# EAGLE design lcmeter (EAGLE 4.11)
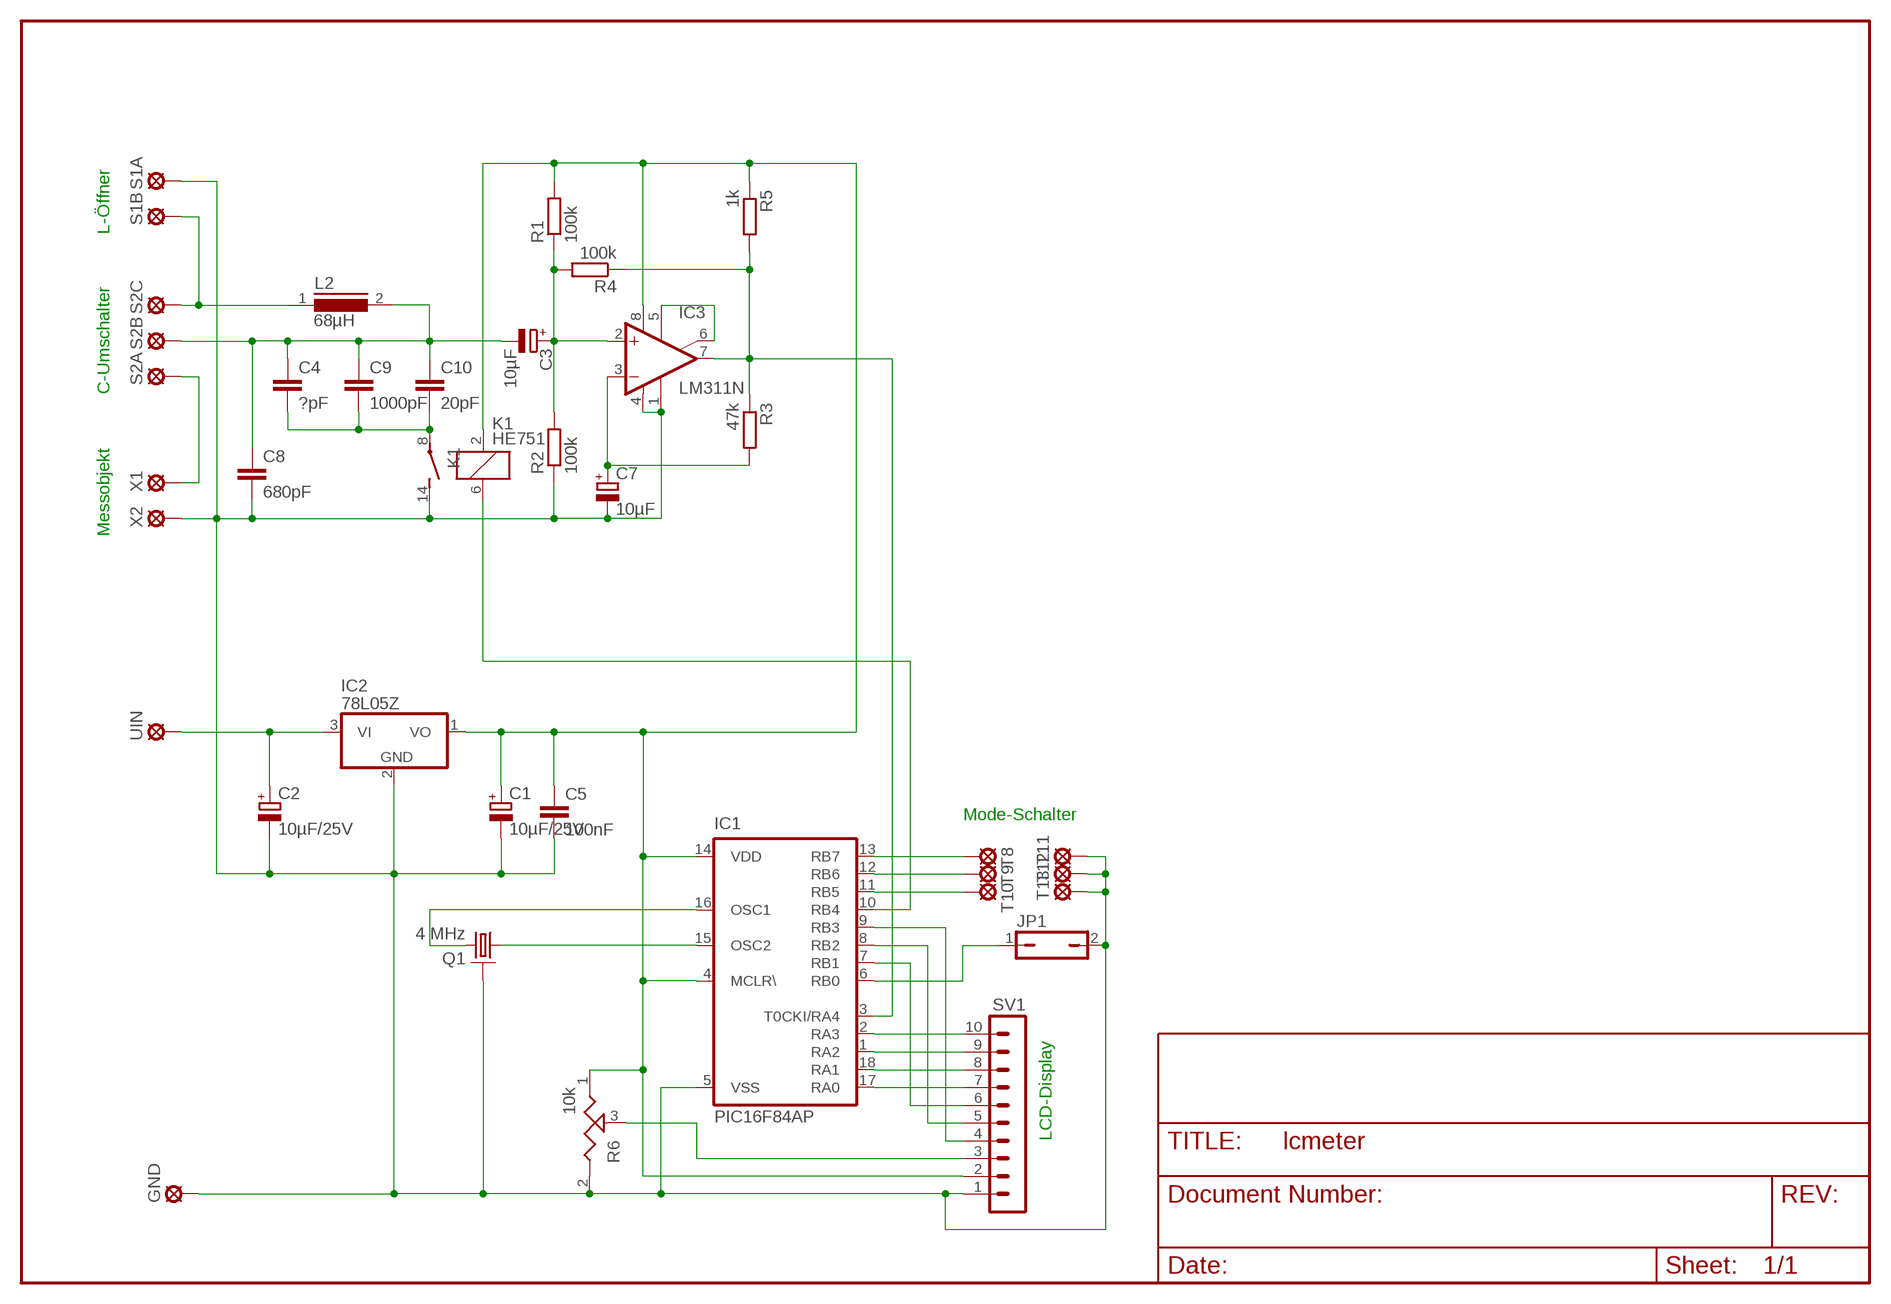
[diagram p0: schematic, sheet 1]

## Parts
C1  10µF/25V  CPOL-EUE2.5-5  [E2,5-5]
C2  10µF/25V  CPOL-EUE2.5-5  [E2,5-5]
C3  10µF  CPOL-EUE5-10.5  [E5-10,5]
C4  ?pF  C-EU150-054X183  [C150-054X183]
C5  100nF  C-EU050-050X075  [C050-050X075]
C7  10µF  CPOL-EUE5-10.5  [E5-10,5]
C8  680pF  C-EU150-054X183  [C150-054X183]
C9  1000pF  C-EU150-054X183  [C150-054X183]
C10  20pF  C-EU150-054X183  [C150-054X183]
GND  LSP10  [LSP10]
IC1  PIC16F84AP  [DIL18]
IC2  78L05Z  [TO92]
IC3  LM311N  [DIL08]
JP1  JP1Q  [JP1]
K1  HE751  [HE751]
L2  68µH  MESC26  [MESC26]
Q1  4 MHz  RESONATOR  [RES3PIN]
R1  100k  R-EU_0309/12  [0309/12]
R2  100k  R-EU_0309/12  [0309/12]
R3  47k  R-EU_0309/12  [0309/12]
R4  100k  R-EU_0309/12  [0309/12]
R5  1k  R-EU_0309/12  [0309/12]
R6  10k  POTUS-L  [PT-10]
S1A  LSP10  [LSP10]
S1B  LSP10  [LSP10]
S2A  LSP10  [LSP10]
S2B  LSP10  [LSP10]
S2C  LSP10  [LSP10]
SV1  MA10-1  [MA10-1]
T8  LSP10  [LSP10]
T9  LSP10  [LSP10]
T10  LSP10  [LSP10]
T11  LSP10  [LSP10]
T12  LSP10  [LSP10]
T13  LSP10  [LSP10]
UIN  LSP10  [LSP10]
X1  LCx1  LSP10  [LSP10]
X2  LSP10  [LSP10]

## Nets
+5V: C1.+ C5.1 IC1.4(MCLR\) IC1.14(VDD) IC2.1(VO) IC3.8(V+) K1.2 R1.2 R5.1 R6.1 SV1.2
GND: C1.- C2.- C5.2 C7.- C8.2 GND.MP IC1.5(VSS) IC2.2(GND) IC3.1(GND) IC3.4(V-) JP1.2 K1.14(2:S) Q1.2 R2.1 R6.2 S1A.MP SV1.1 T11.MP T12.MP T13.MP X2.MP
N$1: IC1.2(RA3) SV1.10
N$2: IC1.1(RA2) SV1.9
N$3: IC1.18(RA1) SV1.8
N$4: IC1.17(RA0) SV1.7
N$5: IC1.7(RB1) SV1.6
N$6: IC1.8(RB2) SV1.5
N$7: IC1.9(RB3) SV1.4
N$8: L2.1 S1B.MP S2C.MP
N$10: C3.+ IC3.2(+IN) R1.1 R2.2 R4.2
N$11: C2.+ IC2.3(VI) UIN.MP
N$12: IC1.15(OSC2) Q1.1
N$13: IC1.16(OSC1) Q1.3
N$14: IC1.6(RB0) JP1.1
N$15: C7.+ IC3.3(-IN) R3.2
N$17: IC3.5(ON) IC3.6(ON/STR)
N$18: IC1.3(T0CKI/RA4) IC3.7(OUT) R3.1 R4.1 R5.2
N$19: C3.- C4.1 C8.1 C9.1 C10.1 L2.2 S2B.MP
N$20: C4.2 C9.2 C10.2 K1.8(2:P)
N$21: IC1.10(RB4) K1.6
N$22: S2A.MP X1.MP
N$23: R6.3 SV1.3
N$25: IC1.13(RB7) T8.MP
N$26: IC1.12(RB6) T9.MP
N$27: IC1.11(RB5) T10.MP

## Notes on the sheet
- L-Öffner
- C-Umschalter
- Messobjekt
- Mode-Schalter
- LCD-Display

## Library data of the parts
C1-C3 C7 = rcl:CPOL-EU: POLARIZED CAPACITOR, European symbol
C4 C5 C8-C10 = rcl:C-EU: CAPACITOR, European symbol
GND S1A S1B S2A S2B S2C T8-T13 UIN X1 X2 = solpad:LSP10: SOLDER PAD
IC1 = microchip:PIC16F8*: MICROCONTROLLER 8-Bit PIC16F8X Family - CMOS Flash/EEPROM Pin Compatible : PIC16F83, PIC16CR83, PIC16F84A, PIC16CR84 see also PIC16C*
IC2 = linear:78*: Positive VOLTAGE REGULATOR
IC3 = linear:LM311: COMPARATOR
JP1 = jumper:JP1Q: JUMPER
K1 = relay:HE751: RELAY reed, 1 x norm. open, Hamlin
L2 = inductors:MESC26: INDUCTOR
Q1 = sprut:RESONATOR: CRYSTAL
R1-R5 = rcl:R-EU_: RESISTOR, European symbol
R6 = discrete:POTUS-L
SV1 = con-lstb:MA10-1: PIN HEADER

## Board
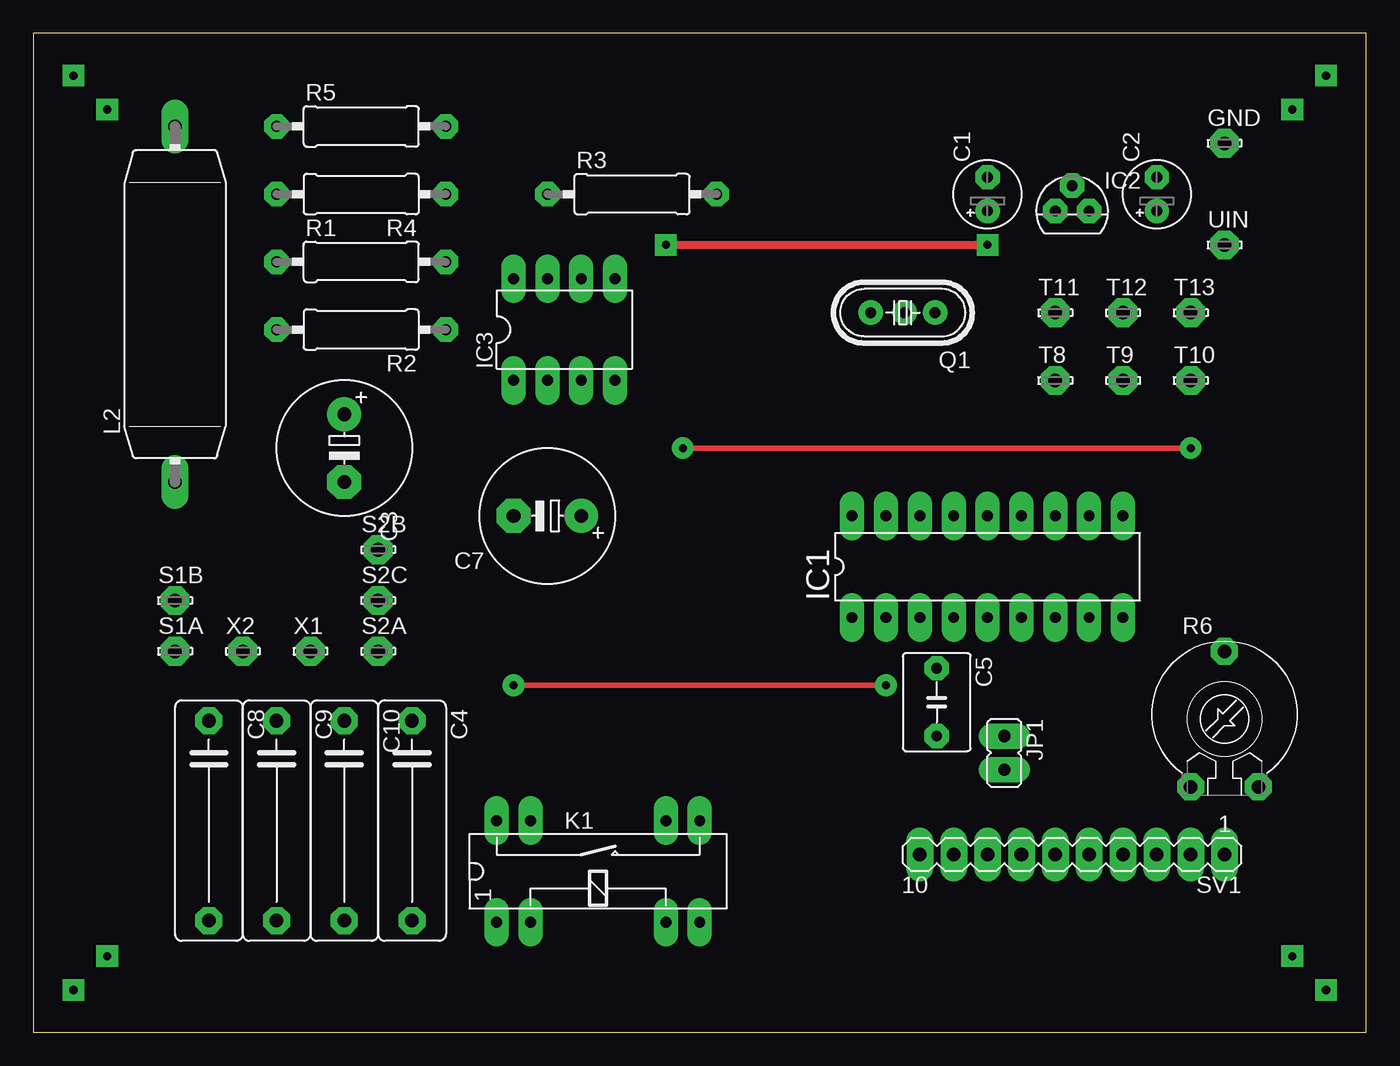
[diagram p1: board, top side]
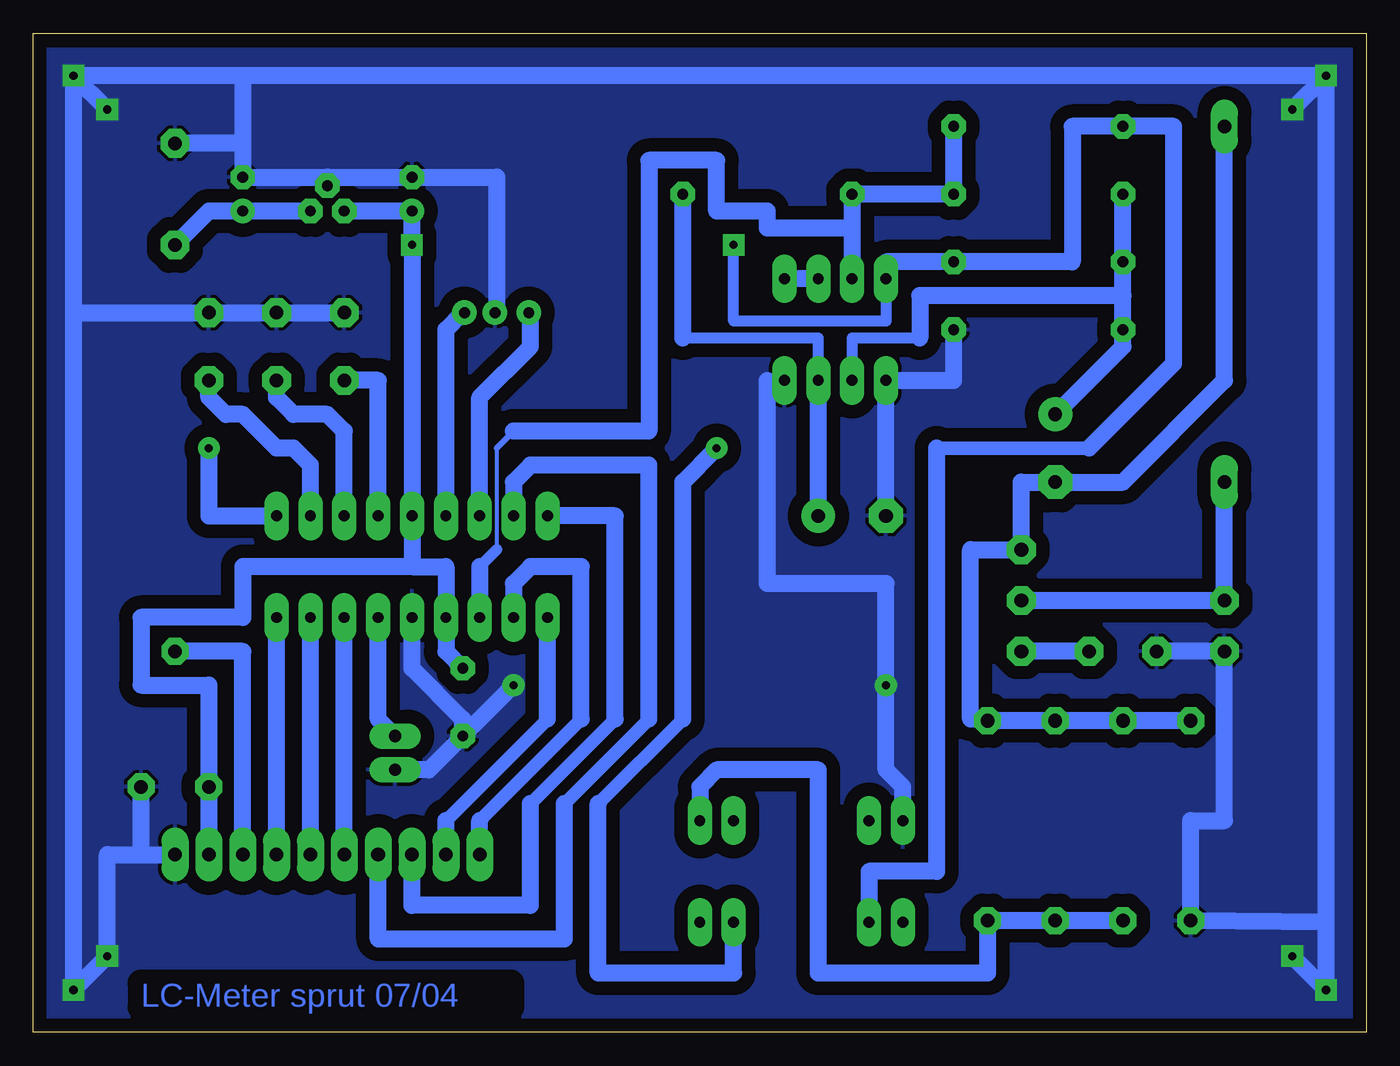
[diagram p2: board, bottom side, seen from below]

Size 100 x 74.92 mm. Coordinates in mm from the lower left corner, seen from the top.
Outline: 0,0 100,0 100,74.92 0,74.92 0,0
Copper layers (1*16): Top 0.035mm / dielectric 1.5mm / Bottom 0.035mm
Design rules "leiterplatte mit löchern": minimum track width 10mil, minimum drill 12mil, track to track 8mil, track to pad 8mil, pad to pad 8mil, via to via 8mil, smd to smd 8mil, copper to edge 40mil, drill to drill 8mil, minimum pad ring 20mil, minimum via ring 20mil, stop-mask expansion 4mil, vias tented up to drill 0mil, thermal gap 10mil

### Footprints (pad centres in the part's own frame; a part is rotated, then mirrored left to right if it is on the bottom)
E2,5-5 = drill 0.813 pad 1.6 round: + -1.27,0 | drill 0.813 pad 1.6 octagon: - 1.27,0
E5-10,5 = drill 1.016 pad 2.54 round: + -2.54,0 | drill 1.016 pad 2.54 octagon: - 2.54,0
C150-054X183 = drill 1.016 octagon: 1 -7.493,0; 2 7.493,0
C050-050X075 = drill 0.813 octagon: 1 -2.54,0; 2 2.54,0
LSP10 = drill 1.016 pad 2.159 octagon: MP 0,0
DIL18 = drill 0.813 long: 1 -10.16,-3.81; 2 -7.62,-3.81; 3 -5.08,-3.81; 4 -2.54,-3.81; 5 0,-3.81; 6 2.54,-3.81; 7 5.08,-3.81; 8 7.62,-3.81; 9 10.16,-3.81; 10 10.16,3.81; 11 7.62,3.81; 12 5.08,3.81; 13 2.54,3.81; 14 0,3.81; 15 -2.54,3.81; 16 -5.08,3.81; 17 -7.62,3.81; 18 -10.16,3.81
TO92 = drill 0.813 octagon: 1 -1.27,0; 2 0,1.905; 3 1.27,0
DIL08 = drill 0.813 long: 1 -3.81,-3.81; 2 -1.27,-3.81; 3 1.27,-3.81; 4 3.81,-3.81; 5 3.81,3.81; 6 1.27,3.81; 7 -1.27,3.81; 8 -3.81,3.81
JP1 = drill 0.914 long: 1 0,-1.27; 2 0,1.27
HE751 = drill 0.813 long: 1 -7.62,-3.81; 2 -5.08,-3.81; 6 5.08,-3.81; 7 7.62,-3.81; 8 7.62,3.81; 9 5.08,3.81; 13 -5.08,3.81; 14 -7.62,3.81
MESC26 = drill 1.016 long: 1 -13.335,0; 2 13.335,0
RES3PIN = drill 0.813 round: 1 -2.413,0; 2 -0.127,0; 3 2.413,0
0309/12 = drill 0.813 octagon: 1 -6.35,0; 2 6.35,0
PT-10 = drill 1.016 pad 1.778 octagon: 1 -2.54,-5.08; 2 2.54,-5.08; 3 0,5.08
MA10-1 = drill 1.016 long: 1 -11.43,0; 2 -8.89,0; 3 -6.35,0; 4 -3.81,0; 5 -1.27,0; 6 1.27,0; 7 3.81,0; 8 6.35,0; 9 8.89,0; 10 11.43,0

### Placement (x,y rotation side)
C1  71.59,62.86 90 top
C2  84.29,62.86 90 top
C3  23.33,43.81 270 top
C4  28.41,15.87 270 top
C5  67.78,24.76 270 top
C7  38.57,38.73 180 top
C8  13.17,15.87 270 top
C9  18.25,15.87 270 top
C10  23.33,15.87 270 top
GND  89.37,66.67 0 top
IC1  71.59,34.92 0 top
IC2  77.94,61.59 0 top
IC3  39.84,52.7 0 top
JP1  72.86,20.95 180 top
K1  42.38,12.06 0 top
L2  10.63,54.61 90 top
Q1  65.24,53.97 180 top
R1  24.6,57.78 0 top
R2  24.6,52.7 180 top
R3  44.92,62.86 0 top
R4  24.6,62.86 180 top
R5  24.6,67.94 0 top
R6  89.37,23.49 0 top
S1A  10.63,28.57 0 top
S1B  10.63,32.38 0 top
S2A  25.87,28.57 0 top
S2B  25.87,36.19 0 top
S2C  25.87,32.38 0 top
SV1  77.94,13.33 180 top
T8  76.67,48.89 0 top
T9  81.75,48.89 0 top
T10  86.83,48.89 0 top
T11  76.67,53.97 0 top
T12  81.75,53.97 0 top
T13  86.83,53.97 0 top
UIN  89.37,59.05 0 top
X1  20.79,28.57 0 top
X2  15.71,28.57 0 top

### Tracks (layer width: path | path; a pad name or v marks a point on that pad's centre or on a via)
+5V  (via drill 0.61)
  Top 0.61: v47.46,59.05 v71.59,59.05
  Bottom 0.813: v47.46,59.05 47.46,53.34 36.03,53.34 IC3.8
  Bottom 1.016: 32.22,43.81 20.79,43.81
  Bottom 1.27: IC3.8 36.03,57.78 R1.2 22.06,57.78 22.06,67.94 R5.1 14.44,67.94 14.44,50.16 20.79,43.81 | 71.59,34.92 69.05,34.92 IC1.4 69.05,28.57 C5.1 | 71.59,34.92 IC1.14 v71.59,59.05 C1.+ IC2.1 | SV1.2 R6.1 86.83,26.03 91.91,26.03 91.91,31.11 84.29,31.11 84.29,34.92 71.59,34.92 | K1.2 37.3,12.06 32.22,12.06 32.22,43.81
GND  (via drill 0.61)
  Top 0.406: v36.03,26.03 v63.97,26.03
  Bottom 0.406: 77.94,64.13 IC2.2 | v3.01,3.17 v5.55,5.71 | v3.01,71.75 v5.55,69.21 | v96.99,3.17 v94.45,5.71 | v96.99,3.17 v94.45,5.71 | v96.99,3.17 v94.45,5.71 | v96.99,71.75 96.99,53.97 96.99,34.92 | T11.MP T12.MP T13.MP | S1A.MP X2.MP S1A.MP
  Bottom 1.27: 65.24,53.97 65.24,64.13 C1.- 77.94,64.13 C2.- 84.29,66.67 | v96.99,71.75 v94.45,69.21 | v3.01,71.75 v5.55,69.21 | v3.01,71.75 84.29,71.75 | v5.55,5.71 v3.01,3.17 3.01,8.25 | 3.01,8.25 v3.01,71.75 | 96.99,53.97 T11.MP | v96.99,71.75 96.99,34.92 v96.99,3.17 v94.45,5.71 94.45,13.33 91.91,13.33 | 84.29,71.75 v96.99,71.75 | 84.29,71.75 84.29,66.67 | 84.29,66.67 GND.MP | 91.91,13.33 SV1.1 | 91.91,13.33 R6.2 | X2.MP S1A.MP 10.63,15.87 13.17,15.87 C8.2 3.01,8.25 | 44.92,48.89 44.92,33.65 36.03,33.65 v36.03,26.03 36.03,19.68 34.76,18.41 K1.14 | IC1.5 71.59,27.3 67.78,23.49 C5.2 | v63.97,26.03 C5.2 | C5.2 70.32,19.68 JP1.2 | R2.1 30.95,48.89 IC3.1 C7.-
  pour Bottom (isolate 1.016): 0.47,0.63 0.47,74.29 99.53,74.29 99.53,0.63
N$1
  Bottom 1.016: 66.51,15.87 58.89,23.49
  Bottom 1.27: IC1.2 63.97,33.65 62.7,34.92 58.89,34.92 58.89,23.49 | SV1.10 66.51,15.87
N$2
  Bottom 1.016: 69.05,15.87 61.43,23.49
  Bottom 1.27: 61.43,23.49 IC1.1 | SV1.9 69.05,15.87
N$3
  Bottom 1.016: 62.7,17.14 56.35,23.49
  Bottom 1.27: IC1.18 56.35,38.73 56.35,23.49 | 62.7,17.14 62.7,9.52 71.59,9.52 SV1.8
N$4
  Bottom 1.016: 60.16,17.14 53.81,23.49
  Bottom 1.27: IC1.17 63.97,41.27 62.7,42.54 53.81,42.54 53.81,23.49 | 60.16,17.14 60.16,6.98 74.13,6.98 SV1.7
N$5
  Bottom 1.27: SV1.6 IC1.7
N$6
  Bottom 1.27: SV1.5 IC1.8
N$7
  Bottom 1.27: SV1.4 IC1.9
N$8
  Bottom 1.27: L2.1 S1B.MP S2C.MP
N$9  (via drill 0.61)
  other vias: 86.83,43.81
N$10
  Bottom 0.813: IC3.2 38.57,52.07 33.49,52.07
  Bottom 1.27: 18.25,55.24 R2.2 18.25,51.43 | 18.25,55.24 R1.1 R4.2 | C3.+ 18.25,51.43 | 33.49,52.07 33.49,55.24 18.25,55.24 | 18.25,51.43 18.25,55.24
N$11
  Bottom 1.27: IC2.3 C2.+ 86.83,61.59 UIN.MP
N$12
  Bottom 0.406: 67.78,53.97 Q1.1
  Bottom 1.27: IC1.15 69.05,52.7 67.78,53.97
N$13
  Bottom 0.406: 62.7,53.97 Q1.3
  Bottom 1.27: IC1.16 66.51,47.62 62.7,51.43 62.7,53.97
N$14
  Bottom 1.27: IC1.6 74.13,23.49 JP1.1
N$15
  Bottom 0.813: 51.27,52.07 41.11,52.07 IC3.3
  Bottom 1.27: 51.27,52.07 R3.2 | C7.+ IC3.3
N$17
  Bottom 1.27: IC3.6 IC3.5
N$18
  Bottom 0.305: 65.24,43.81 65.24,36.19
  Bottom 0.406: 63.97,45.08 65.24,43.81
  Bottom 0.813: 65.24,36.19 66.51,34.92
  Bottom 1.27: R3.1 38.57,60.32 44.92,60.32 44.92,61.59 48.73,61.59 48.73,65.4 53.81,65.4 53.81,45.08 63.97,45.08 | 66.51,34.92 IC1.3 | R3.1 IC3.7 | R3.1 R4.1 R5.2
N$19
  Bottom 0.406: C4.1 28.41,23.49 | C10.1 23.33,23.49 23.46,23.36 | 18.25,23.49 C9.1 | 18.25,23.49 18.38,23.36 | 18.12,23.36 18.25,23.49
  Bottom 1.27: L2.2 10.63,48.89 18.25,41.27 C3.- 25.87,41.27 S2B.MP 29.68,36.19 29.68,23.49 28.41,23.49 | 23.46,23.36 C4.1 | 18.38,23.36 C10.1 | C8.1 18.12,23.36
N$20
  Bottom 0.406: C10.2 23.33,8.25 23.2,8.38 | C4.2 28.41,8.25 28.28,8.38
  Bottom 1.27: C9.2 23.2,8.38 | C10.2 28.28,8.38 | C4.2 28.41,4.44 41.11,4.44 41.11,19.68 48.73,19.68 50,18.41 K1.8
N$21  (via drill 0.61)
  Top 0.406: v48.73,43.81 v86.83,43.81
  Bottom 1.016: 57.62,17.14 51.27,23.49
  Bottom 1.27: IC1.10 86.83,38.73 v86.83,43.81 | 51.27,23.49 51.27,41.27 v48.73,43.81 | 57.62,17.14 57.62,4.44 47.46,4.44 K1.6
N$22
  Bottom 1.27: X1.MP S2A.MP
N$23
  Bottom 1.27: SV1.3 84.29,28.57 R6.3
N$25
  Bottom 1.27: IC1.13 74.13,48.89 T8.MP
N$26
  Bottom 1.27: IC1.12 76.67,45.08 77.94,46.35 80.48,46.35 81.75,47.62 T9.MP
N$27
  Bottom 1.27: IC1.11 79.21,42.54 80.48,43.81 81.75,43.81 84.29,46.35 85.56,46.35 86.83,47.62 T10.MP

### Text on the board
Bottom: LC-Meter sprut 07/04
